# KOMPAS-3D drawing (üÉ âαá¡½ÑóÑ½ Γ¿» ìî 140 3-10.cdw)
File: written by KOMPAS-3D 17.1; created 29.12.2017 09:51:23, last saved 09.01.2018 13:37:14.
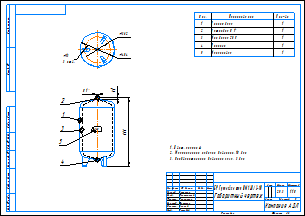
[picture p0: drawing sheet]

Sheet 1: A3, landscape, title-block layout from C:\Лощинин\GRAPHIC.LYT style 1

Title block, sheet 1: name: БР Гранлевел тип НМ 140/3-10 / Габаритный чертеж; mass: 25,3; sheets: 1; sheet format: A3; stored path: \\Fsk1\files\АП\20_PKO\02_Насосное направление\Разработка\04_Проекты разные\Баки\КД действующая\Баки Flexcon R\Компас\Чертежи\БР Гранлевел тип НМ 140 1,5-6.cdw; drawn by: Лощинин; checked by: Хантимеров

Views: Проекционный вид 3
Referenced files in \\Fsk1\files\АП\20_PKO\02_Насосное направление\Разработка\04_Проекты разные\Баки\КД действующая\Баки Flexcon R\Компас\: 140 литров.a3d, 16146_Flexcon_140_1-6.m3d
Referenced files in C:\Лощинин\: GRAPHIC.LYT
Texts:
  IvAn
  ADL
  Поз.
  Кол-во
  Корпус бака
  Мембрана SBR
  Патрубок G 1"
  Ниппель
  Маркировка
  АДЛ
  БР Гранлевел тип НМ 140/1,5-6
  Цвет: красный
  Максимальное рабочее давление: 10 бар
  Предварительное давление газа: 3 бар
  ACAD_ISO03W100_RGB_223_127_255_SC_0.063_THICK_0.05
  ACAD_ISO03W100_RGB_223_127_255_SC_1_THICK_0.05
  Лит-Масса-Масштаб
  Материал-Предприятие
  Масштаб
  Изм.
  Лист
  № докум.
  Подп.
  Дата
  Лит.
  Разраб.
  Пров.
  Т.контр.
  Курлыкина
  Листов
  Нач.отд.
  Щетинин
  Н.контр.
  Долгов
  Утв.
  Рашидов
  Компания АДЛ
  Изменение
  Номер документа
  Подпись
  Обозначение документа
  Наименование изделия
  Масса изделия по ГОСТ 2.109-73
  Порядковый номер листа
  Общее количество листов в документе
  Характер работы, выполненной лицом, подписавшим документ
  Наименование или индекс предприятия, выпускающего документ
  Инв. № подл.
  Подп. и дата
  Взам. инв. №
  Инв. № дубл.
  Инвентарный номер подлинника по ГОСТ 2.501-68
  Подпись принявшего подлинник в отдел технической документации
  Инвентарный номер подлинника, взамен которого выпущен данный подлинник
  Инвентарный номер дубликата по ГОСТ 2.502-68
  Подпись принявшего дубликат в отдел технической документации
  Справ. №
  Перв. примен.
  Обозначение документа, взамен или на основании которого выпущен данный документ
  Обозначение документа, в котором впервые записан данный документ
  Подпись лица, копировавшего чертеж
  Обозначение формата листа
Dimensions and other numbers on the sheet: 1; 3; 2; 4; 5; 950; 21; 1:10; 25,3; 16146_Flexcon_140_1-6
